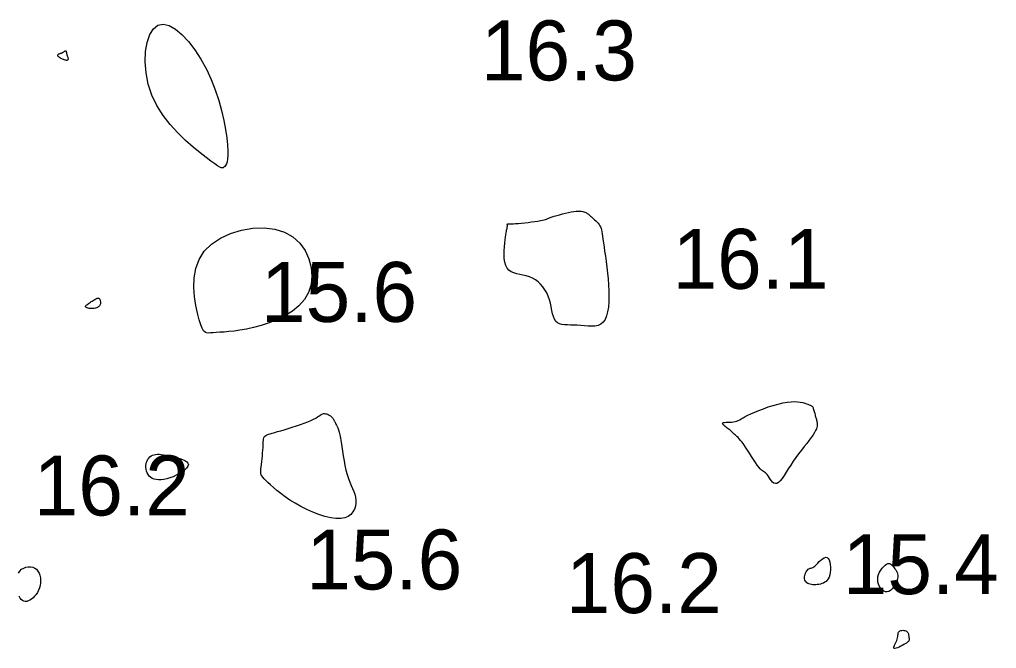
# Model space of a CAD drawing. Extents: x 3040093 to 3056816, y 408076 to 509144.
# Drawn here: x 3045759.4 to 3045840.9, y 434343.9 to 434396.4 of the extents above; entities that cross this region are included whole.
import ezdxf

# ---------------------------------------------------------------- set-up
doc = ezdxf.new("R2010")
doc.units = 0
doc.layers.add('V-CHAN-CONT-EL17', color=7, linetype='Continuous')
doc.layers.add('V-TOPO-SOUN-0610', color=7, linetype='Continuous')

msp = doc.modelspace()

# ---------------------------------------------------------------- linework, layer by layer
at = {"layer": 'V-CHAN-CONT-EL17'}
for points in [[(3045770.173, 434390.988), (3045769.99, 434391.923), (3045769.919, 434392.837), (3045769.953, 434393.698), (3045770.083, 434394.471), (3045770.303, 434395.12), (3045770.605, 434395.611), (3045770.98, 434395.91), (3045771.421, 434395.991), (3045771.912, 434395.869), (3045772.438, 434395.569), (3045772.982, 434395.114), (3045773.528, 434394.53), (3045774.062, 434393.84), (3045774.565, 434393.069), (3045775.024, 434392.241), (3045775.424, 434391.379), (3045775.767, 434390.503), (3045776.054, 434389.63), (3045776.29, 434388.777), (3045776.479, 434387.962), (3045776.622, 434387.203), (3045776.724, 434386.518), (3045776.788, 434385.925), (3045776.817, 434385.435), (3045776.816, 434385.043), (3045776.791, 434384.736), (3045776.748, 434384.502), (3045776.69, 434384.329), (3045776.623, 434384.206), (3045776.554, 434384.121), (3045776.486, 434384.061), (3045776.422, 434384.018), (3045776.352, 434383.998), (3045776.26, 434384.01), (3045776.134, 434384.063), (3045775.959, 434384.166), (3045775.721, 434384.329), (3045775.407, 434384.561), (3045775.001, 434384.87), (3045774.497, 434385.264), (3045773.918, 434385.74), (3045773.292, 434386.294), (3045772.648, 434386.922), (3045772.016, 434387.617), (3045771.423, 434388.377), (3045770.9, 434389.196), (3045770.476, 434390.07)], [(3045763.036, 434393.063), (3045762.964, 434393.098), (3045762.894, 434393.137), (3045762.827, 434393.177), (3045762.767, 434393.219), (3045762.715, 434393.261), (3045762.674, 434393.302), (3045762.646, 434393.341), (3045762.633, 434393.377), (3045762.633, 434393.41), (3045762.644, 434393.439), (3045762.664, 434393.466), (3045762.691, 434393.489), (3045762.723, 434393.51), (3045762.758, 434393.527), (3045762.793, 434393.541), (3045762.827, 434393.553), (3045762.86, 434393.562), (3045762.893, 434393.571), (3045762.925, 434393.579), (3045762.956, 434393.588), (3045762.988, 434393.599), (3045763.02, 434393.613), (3045763.053, 434393.63), (3045763.086, 434393.652), (3045763.12, 434393.676), (3045763.154, 434393.701), (3045763.186, 434393.725), (3045763.216, 434393.746), (3045763.244, 434393.763), (3045763.268, 434393.772), (3045763.289, 434393.773), (3045763.305, 434393.764), (3045763.317, 434393.746), (3045763.326, 434393.718), (3045763.335, 434393.683), (3045763.343, 434393.641), (3045763.352, 434393.593), (3045763.363, 434393.539), (3045763.377, 434393.481), (3045763.395, 434393.419), (3045763.416, 434393.356), (3045763.437, 434393.293), (3045763.456, 434393.231), (3045763.472, 434393.172), (3045763.482, 434393.118), (3045763.485, 434393.071), (3045763.479, 434393.032), (3045763.461, 434393.003), (3045763.433, 434392.983), (3045763.396, 434392.972), (3045763.351, 434392.97), (3045763.298, 434392.975), (3045763.239, 434392.988), (3045763.175, 434393.007), (3045763.107, 434393.032)], [(3045805.664, 434370.898), (3045805.391, 434370.901), (3045805.134, 434370.904), (3045804.896, 434370.915), (3045804.679, 434370.943), (3045804.485, 434370.996), (3045804.317, 434371.081), (3045804.177, 434371.209), (3045804.065, 434371.383), (3045803.977, 434371.599), (3045803.904, 434371.848), (3045803.841, 434372.123), (3045803.78, 434372.414), (3045803.713, 434372.714), (3045803.634, 434373.014), (3045803.535, 434373.306), (3045803.412, 434373.583), (3045803.264, 434373.842), (3045803.093, 434374.081), (3045802.901, 434374.299), (3045802.691, 434374.493), (3045802.463, 434374.662), (3045802.221, 434374.803), (3045801.965, 434374.916), (3045801.7, 434374.999), (3045801.429, 434375.063), (3045801.162, 434375.118), (3045800.903, 434375.174), (3045800.661, 434375.244), (3045800.442, 434375.338), (3045800.253, 434375.467), (3045800.1, 434375.642), (3045799.989, 434375.87), (3045799.915, 434376.142), (3045799.873, 434376.447), (3045799.858, 434376.77), (3045799.863, 434377.1), (3045799.882, 434377.424), (3045799.911, 434377.728), (3045799.943, 434378.002), (3045799.973, 434378.234), (3045800, 434378.426), (3045800.025, 434378.584), (3045800.047, 434378.711), (3045800.067, 434378.812), (3045800.084, 434378.892), (3045800.098, 434378.955), (3045800.109, 434379.006), (3045800.117, 434379.048), (3045800.123, 434379.084), (3045800.127, 434379.115), (3045800.129, 434379.141), (3045800.129, 434379.163), (3045800.129, 434379.184), (3045800.128, 434379.203), (3045800.126, 434379.222), (3045800.125, 434379.241), (3045800.123, 434379.261), (3045800.123, 434379.281), (3045800.125, 434379.299), (3045800.128, 434379.316), (3045800.134, 434379.33), (3045800.143, 434379.34), (3045800.155, 434379.347), (3045800.172, 434379.349), (3045800.198, 434379.348), (3045800.238, 434379.346), (3045800.297, 434379.343), (3045800.38, 434379.341), (3045800.491, 434379.342), (3045800.636, 434379.347), (3045800.819, 434379.358), (3045801.044, 434379.376), (3045801.301, 434379.4), (3045801.578, 434379.429), (3045801.866, 434379.461), (3045802.152, 434379.496), (3045802.426, 434379.533), (3045802.675, 434379.569), (3045802.89, 434379.605), (3045803.062, 434379.638), (3045803.197, 434379.671), (3045803.308, 434379.704), (3045803.404, 434379.739), (3045803.496, 434379.776), (3045803.594, 434379.817), (3045803.71, 434379.863), (3045803.853, 434379.915), (3045804.032, 434379.974), (3045804.24, 434380.037), (3045804.471, 434380.103), (3045804.716, 434380.167), (3045804.966, 434380.229), (3045805.214, 434380.284), (3045805.452, 434380.331), (3045805.672, 434380.366), (3045805.866, 434380.387), (3045806.036, 434380.396), (3045806.184, 434380.394), (3045806.312, 434380.383), (3045806.423, 434380.365), (3045806.518, 434380.34), (3045806.599, 434380.311), (3045806.67, 434380.279), (3045806.731, 434380.246), (3045806.787, 434380.211), (3045806.839, 434380.174), (3045806.889, 434380.132), (3045806.942, 434380.087), (3045806.998, 434380.036), (3045807.061, 434379.979), (3045807.133, 434379.915), (3045807.217, 434379.843), (3045807.308, 434379.765), (3045807.405, 434379.68), (3045807.504, 434379.589), (3045807.601, 434379.494), (3045807.692, 434379.395), (3045807.776, 434379.292), (3045807.847, 434379.186), (3045807.904, 434379.078), (3045807.949, 434378.961), (3045807.985, 434378.831), (3045808.015, 434378.681), (3045808.042, 434378.505), (3045808.07, 434378.298), (3045808.101, 434378.052), (3045808.14, 434377.764), (3045808.187, 434377.427), (3045808.241, 434377.048), (3045808.3, 434376.633), (3045808.36, 434376.188), (3045808.419, 434375.721), (3045808.474, 434375.237), (3045808.522, 434374.744), (3045808.559, 434374.249), (3045808.585, 434373.758), (3045808.594, 434373.279), (3045808.583, 434372.822), (3045808.55, 434372.393), (3045808.49, 434372.001), (3045808.4, 434371.655), (3045808.277, 434371.363), (3045808.117, 434371.133), (3045807.919, 434370.97), (3045807.687, 434370.867), (3045807.428, 434370.812), (3045807.148, 434370.795), (3045806.854, 434370.805), (3045806.552, 434370.831), (3045806.249, 434370.861), (3045805.951, 434370.886)], [(3045775.446, 434377.648), (3045776.188, 434378.147), (3045777.036, 434378.54), (3045777.953, 434378.819), (3045778.899, 434378.976), (3045779.839, 434379.003), (3045780.733, 434378.894), (3045781.544, 434378.641), (3045782.24, 434378.242), (3045782.813, 434377.721), (3045783.26, 434377.105), (3045783.581, 434376.423), (3045783.772, 434375.704), (3045783.831, 434374.977), (3045783.757, 434374.27), (3045783.547, 434373.612), (3045783.204, 434373.025), (3045782.747, 434372.512), (3045782.2, 434372.067), (3045781.587, 434371.685), (3045780.931, 434371.362), (3045780.257, 434371.094), (3045779.588, 434370.875), (3045778.948, 434370.701), (3045778.356, 434370.568), (3045777.817, 434370.469), (3045777.327, 434370.398), (3045776.887, 434370.35), (3045776.494, 434370.318), (3045776.148, 434370.297), (3045775.847, 434370.279), (3045775.591, 434370.261), (3045775.376, 434370.238), (3045775.196, 434370.225), (3045775.044, 434370.24), (3045774.911, 434370.3), (3045774.79, 434370.423), (3045774.674, 434370.626), (3045774.554, 434370.928), (3045774.423, 434371.344), (3045774.279, 434371.887), (3045774.141, 434372.534), (3045774.034, 434373.258), (3045773.984, 434374.031), (3045774.015, 434374.825), (3045774.153, 434375.611), (3045774.422, 434376.362), (3045774.849, 434377.049)], [(3045765.348, 434372.796), (3045765.427, 434372.849), (3045765.506, 434372.901), (3045765.583, 434372.95), (3045765.657, 434372.997), (3045765.727, 434373.04), (3045765.791, 434373.077), (3045765.85, 434373.108), (3045765.9, 434373.131), (3045765.944, 434373.147), (3045765.982, 434373.154), (3045766.015, 434373.154), (3045766.043, 434373.146), (3045766.069, 434373.13), (3045766.093, 434373.105), (3045766.115, 434373.072), (3045766.137, 434373.031), (3045766.158, 434372.982), (3045766.175, 434372.928), (3045766.189, 434372.869), (3045766.196, 434372.807), (3045766.197, 434372.744), (3045766.19, 434372.68), (3045766.173, 434372.618), (3045766.145, 434372.559), (3045766.107, 434372.503), (3045766.059, 434372.451), (3045766, 434372.405), (3045765.932, 434372.364), (3045765.855, 434372.329), (3045765.768, 434372.302), (3045765.673, 434372.283), (3045765.57, 434372.272), (3045765.463, 434372.269), (3045765.356, 434372.274), (3045765.253, 434372.286), (3045765.159, 434372.303), (3045765.077, 434372.326), (3045765.012, 434372.354), (3045764.967, 434372.386), (3045764.947, 434372.421), (3045764.95, 434372.46), (3045764.971, 434372.501), (3045765.01, 434372.546), (3045765.061, 434372.592), (3045765.124, 434372.641), (3045765.195, 434372.691), (3045765.27, 434372.743)], [(3045821.718, 434358.525), (3045821.647, 434358.586), (3045821.575, 434358.636), (3045821.5, 434358.682), (3045821.418, 434358.736), (3045821.327, 434358.807), (3045821.223, 434358.905), (3045821.104, 434359.04), (3045820.967, 434359.219), (3045820.816, 434359.435), (3045820.655, 434359.678), (3045820.488, 434359.937), (3045820.318, 434360.202), (3045820.151, 434360.463), (3045819.99, 434360.71), (3045819.839, 434360.933), (3045819.701, 434361.123), (3045819.577, 434361.282), (3045819.465, 434361.414), (3045819.364, 434361.524), (3045819.274, 434361.615), (3045819.192, 434361.69), (3045819.119, 434361.755), (3045819.053, 434361.812), (3045818.992, 434361.866), (3045818.936, 434361.918), (3045818.88, 434361.969), (3045818.825, 434362.02), (3045818.767, 434362.072), (3045818.704, 434362.126), (3045818.634, 434362.184), (3045818.555, 434362.246), (3045818.466, 434362.313), (3045818.373, 434362.382), (3045818.282, 434362.453), (3045818.199, 434362.522), (3045818.133, 434362.587), (3045818.088, 434362.646), (3045818.072, 434362.696), (3045818.092, 434362.735), (3045818.152, 434362.761), (3045818.246, 434362.777), (3045818.368, 434362.787), (3045818.51, 434362.793), (3045818.664, 434362.798), (3045818.824, 434362.807), (3045818.98, 434362.822), (3045819.127, 434362.847), (3045819.26, 434362.884), (3045819.384, 434362.933), (3045819.508, 434362.996), (3045819.641, 434363.071), (3045819.793, 434363.159), (3045819.971, 434363.26), (3045820.186, 434363.373), (3045820.445, 434363.499), (3045820.754, 434363.636), (3045821.105, 434363.78), (3045821.487, 434363.925), (3045821.888, 434364.066), (3045822.297, 434364.197), (3045822.702, 434364.312), (3045823.092, 434364.406), (3045823.456, 434364.474), (3045823.784, 434364.51), (3045824.076, 434364.52), (3045824.335, 434364.507), (3045824.562, 434364.477), (3045824.759, 434364.436), (3045824.929, 434364.387), (3045825.074, 434364.338), (3045825.195, 434364.292), (3045825.295, 434364.253), (3045825.376, 434364.221), (3045825.442, 434364.192), (3045825.494, 434364.164), (3045825.535, 434364.134), (3045825.569, 434364.1), (3045825.596, 434364.058), (3045825.621, 434364.006), (3045825.646, 434363.943), (3045825.67, 434363.869), (3045825.693, 434363.787), (3045825.717, 434363.7), (3045825.741, 434363.609), (3045825.764, 434363.517), (3045825.787, 434363.426), (3045825.811, 434363.339), (3045825.834, 434363.258), (3045825.856, 434363.181), (3045825.878, 434363.107), (3045825.899, 434363.035), (3045825.918, 434362.964), (3045825.935, 434362.893), (3045825.95, 434362.82), (3045825.962, 434362.744), (3045825.97, 434362.663), (3045825.972, 434362.575), (3045825.963, 434362.477), (3045825.939, 434362.366), (3045825.898, 434362.24), (3045825.834, 434362.096), (3045825.744, 434361.932), (3045825.624, 434361.743), (3045825.473, 434361.529), (3045825.294, 434361.292), (3045825.094, 434361.034), (3045824.877, 434360.759), (3045824.65, 434360.47), (3045824.419, 434360.169), (3045824.19, 434359.859), (3045823.968, 434359.544), (3045823.758, 434359.227), (3045823.561, 434358.917), (3045823.376, 434358.623), (3045823.203, 434358.352), (3045823.039, 434358.116), (3045822.886, 434357.922), (3045822.743, 434357.779), (3045822.608, 434357.697), (3045822.481, 434357.68), (3045822.362, 434357.721), (3045822.25, 434357.805), (3045822.145, 434357.921), (3045822.048, 434358.055), (3045821.956, 434358.195), (3045821.871, 434358.327), (3045821.792, 434358.44)], [(3045781.987, 434356.304), (3045781.588, 434356.574), (3045781.226, 434356.84), (3045780.901, 434357.097), (3045780.614, 434357.341), (3045780.364, 434357.566), (3045780.151, 434357.769), (3045779.975, 434357.944), (3045779.835, 434358.088), (3045779.728, 434358.209), (3045779.651, 434358.313), (3045779.599, 434358.41), (3045779.569, 434358.508), (3045779.557, 434358.615), (3045779.558, 434358.74), (3045779.57, 434358.891), (3045779.588, 434359.073), (3045779.611, 434359.282), (3045779.637, 434359.511), (3045779.664, 434359.751), (3045779.69, 434359.996), (3045779.715, 434360.236), (3045779.735, 434360.466), (3045779.75, 434360.678), (3045779.759, 434360.865), (3045779.764, 434361.028), (3045779.768, 434361.17), (3045779.776, 434361.292), (3045779.79, 434361.397), (3045779.814, 434361.487), (3045779.852, 434361.564), (3045779.906, 434361.63), (3045779.981, 434361.688), (3045780.077, 434361.74), (3045780.198, 434361.79), (3045780.344, 434361.839), (3045780.518, 434361.89), (3045780.72, 434361.947), (3045780.954, 434362.011), (3045781.221, 434362.087), (3045781.52, 434362.174), (3045781.844, 434362.273), (3045782.183, 434362.38), (3045782.526, 434362.492), (3045782.864, 434362.608), (3045783.186, 434362.724), (3045783.483, 434362.838), (3045783.744, 434362.948), (3045783.963, 434363.051), (3045784.142, 434363.146), (3045784.289, 434363.232), (3045784.408, 434363.308), (3045784.506, 434363.373), (3045784.59, 434363.427), (3045784.665, 434363.469), (3045784.737, 434363.497), (3045784.812, 434363.511), (3045784.888, 434363.513), (3045784.966, 434363.504), (3045785.043, 434363.485), (3045785.119, 434363.459), (3045785.191, 434363.428), (3045785.259, 434363.392), (3045785.321, 434363.354), (3045785.377, 434363.316), (3045785.426, 434363.277), (3045785.468, 434363.238), (3045785.506, 434363.199), (3045785.539, 434363.161), (3045785.567, 434363.124), (3045785.592, 434363.088), (3045785.614, 434363.053), (3045785.633, 434363.02), (3045785.651, 434362.987), (3045785.669, 434362.953), (3045785.687, 434362.917), (3045785.708, 434362.876), (3045785.731, 434362.831), (3045785.759, 434362.778), (3045785.792, 434362.717), (3045785.831, 434362.645), (3045785.876, 434362.559), (3045785.925, 434362.453), (3045785.978, 434362.323), (3045786.033, 434362.164), (3045786.09, 434361.971), (3045786.147, 434361.738), (3045786.204, 434361.462), (3045786.259, 434361.141), (3045786.315, 434360.781), (3045786.374, 434360.394), (3045786.436, 434359.99), (3045786.504, 434359.581), (3045786.58, 434359.177), (3045786.666, 434358.788), (3045786.763, 434358.425), (3045786.873, 434358.097), (3045786.99, 434357.8), (3045787.108, 434357.526), (3045787.221, 434357.272), (3045787.323, 434357.029), (3045787.407, 434356.791), (3045787.469, 434356.553), (3045787.501, 434356.308), (3045787.498, 434356.053), (3045787.456, 434355.795), (3045787.372, 434355.544), (3045787.244, 434355.31), (3045787.069, 434355.104), (3045786.842, 434354.936), (3045786.562, 434354.816), (3045786.226, 434354.754), (3045785.832, 434354.757), (3045785.391, 434354.821), (3045784.914, 434354.937), (3045784.414, 434355.098), (3045783.903, 434355.297), (3045783.392, 434355.524), (3045782.895, 434355.773), (3045782.423, 434356.036)], [(3045770.251, 434358.308), (3045770.156, 434358.432), (3045770.081, 434358.57), (3045770.026, 434358.716), (3045769.991, 434358.869), (3045769.974, 434359.024), (3045769.974, 434359.176), (3045769.993, 434359.324), (3045770.028, 434359.462), (3045770.079, 434359.59), (3045770.145, 434359.707), (3045770.224, 434359.812), (3045770.317, 434359.903), (3045770.421, 434359.98), (3045770.535, 434360.041), (3045770.659, 434360.086), (3045770.792, 434360.115), (3045770.935, 434360.127), (3045771.089, 434360.125), (3045771.255, 434360.11), (3045771.434, 434360.084), (3045771.629, 434360.048), (3045771.839, 434360.005), (3045772.067, 434359.954), (3045772.311, 434359.898), (3045772.561, 434359.836), (3045772.806, 434359.766), (3045773.033, 434359.687), (3045773.23, 434359.598), (3045773.385, 434359.498), (3045773.487, 434359.385), (3045773.522, 434359.259), (3045773.483, 434359.119), (3045773.377, 434358.968), (3045773.216, 434358.813), (3045773.01, 434358.659), (3045772.772, 434358.509), (3045772.512, 434358.371), (3045772.243, 434358.248), (3045771.975, 434358.146), (3045771.718, 434358.069), (3045771.474, 434358.017), (3045771.246, 434357.99), (3045771.034, 434357.986), (3045770.839, 434358.007), (3045770.662, 434358.05), (3045770.504, 434358.115), (3045770.367, 434358.201)], [(3045825.185, 434349.361), (3045825.107, 434349.417), (3045825.041, 434349.483), (3045824.987, 434349.556), (3045824.947, 434349.637), (3045824.92, 434349.724), (3045824.908, 434349.817), (3045824.912, 434349.914), (3045824.93, 434350.014), (3045824.962, 434350.115), (3045825.005, 434350.213), (3045825.056, 434350.307), (3045825.111, 434350.393), (3045825.169, 434350.468), (3045825.227, 434350.53), (3045825.282, 434350.575), (3045825.332, 434350.603), (3045825.379, 434350.617), (3045825.427, 434350.626), (3045825.478, 434350.635), (3045825.535, 434350.651), (3045825.601, 434350.68), (3045825.68, 434350.73), (3045825.774, 434350.805), (3045825.885, 434350.911), (3045826.01, 434351.037), (3045826.143, 434351.17), (3045826.282, 434351.3), (3045826.42, 434351.412), (3045826.553, 434351.494), (3045826.677, 434351.535), (3045826.788, 434351.521), (3045826.88, 434351.444), (3045826.954, 434351.312), (3045827.01, 434351.138), (3045827.047, 434350.934), (3045827.066, 434350.712), (3045827.066, 434350.484), (3045827.048, 434350.263), (3045827.012, 434350.061), (3045826.958, 434349.888), (3045826.887, 434349.743), (3045826.802, 434349.624), (3045826.705, 434349.527), (3045826.598, 434349.449), (3045826.482, 434349.388), (3045826.36, 434349.34), (3045826.233, 434349.303), (3045826.105, 434349.273), (3045825.975, 434349.252), (3045825.847, 434349.239), (3045825.721, 434349.235), (3045825.599, 434349.24), (3045825.483, 434349.255), (3045825.374, 434349.28), (3045825.275, 434349.315)], [(3045831.658, 434348.656), (3045831.515, 434348.715), (3045831.38, 434348.814), (3045831.259, 434348.948), (3045831.157, 434349.109), (3045831.079, 434349.291), (3045831.03, 434349.488), (3045831.015, 434349.692), (3045831.038, 434349.897), (3045831.093, 434350.099), (3045831.175, 434350.292), (3045831.277, 434350.471), (3045831.393, 434350.633), (3045831.515, 434350.772), (3045831.638, 434350.884), (3045831.754, 434350.964), (3045831.859, 434351.008), (3045831.954, 434351.019), (3045832.039, 434351.003), (3045832.117, 434350.964), (3045832.189, 434350.905), (3045832.257, 434350.832), (3045832.323, 434350.749), (3045832.388, 434350.661), (3045832.454, 434350.57), (3045832.518, 434350.477), (3045832.577, 434350.378), (3045832.626, 434350.272), (3045832.663, 434350.157), (3045832.683, 434350.031), (3045832.684, 434349.892), (3045832.663, 434349.737), (3045832.615, 434349.567), (3045832.545, 434349.389), (3045832.454, 434349.211), (3045832.346, 434349.043), (3045832.224, 434348.894), (3045832.091, 434348.771), (3045831.951, 434348.685), (3045831.805, 434348.645)], [(3045832.349, 434343.957), (3045832.346, 434344.006), (3045832.368, 434344.075), (3045832.406, 434344.161), (3045832.456, 434344.259), (3045832.51, 434344.367), (3045832.564, 434344.48), (3045832.609, 434344.596), (3045832.642, 434344.711), (3045832.665, 434344.823), (3045832.682, 434344.931), (3045832.696, 434345.033), (3045832.712, 434345.126), (3045832.732, 434345.21), (3045832.763, 434345.283), (3045832.806, 434345.343), (3045832.864, 434345.388), (3045832.936, 434345.419), (3045833.017, 434345.437), (3045833.102, 434345.443), (3045833.19, 434345.438), (3045833.274, 434345.422), (3045833.353, 434345.397), (3045833.42, 434345.362), (3045833.475, 434345.32), (3045833.517, 434345.272), (3045833.548, 434345.218), (3045833.571, 434345.162), (3045833.587, 434345.105), (3045833.597, 434345.048), (3045833.604, 434344.993), (3045833.609, 434344.942), (3045833.614, 434344.896), (3045833.62, 434344.854), (3045833.624, 434344.817), (3045833.628, 434344.782), (3045833.631, 434344.75), (3045833.633, 434344.719), (3045833.633, 434344.689), (3045833.631, 434344.659), (3045833.626, 434344.629), (3045833.616, 434344.597), (3045833.599, 434344.562), (3045833.572, 434344.524), (3045833.533, 434344.481), (3045833.478, 434344.434), (3045833.406, 434344.381), (3045833.313, 434344.32), (3045833.199, 434344.253), (3045833.069, 434344.183), (3045832.932, 434344.113), (3045832.793, 434344.049), (3045832.662, 434343.994), (3045832.545, 434343.954), (3045832.449, 434343.931), (3045832.382, 434343.931)]]:
    msp.add_lwpolyline(points, close=True, dxfattribs=at)
msp.add_lwpolyline([(3045759.341, 434350.206), (3045759.463, 434350.386), (3045759.615, 434350.53), (3045759.788, 434350.64), (3045759.975, 434350.713), (3045760.168, 434350.75), (3045760.36, 434350.75), (3045760.543, 434350.714), (3045760.709, 434350.64), (3045760.852, 434350.53), (3045760.97, 434350.388), (3045761.064, 434350.22), (3045761.133, 434350.032), (3045761.176, 434349.829), (3045761.195, 434349.617), (3045761.189, 434349.402), (3045761.157, 434349.19), (3045761.101, 434348.985), (3045761.022, 434348.79), (3045760.926, 434348.608), (3045760.815, 434348.44), (3045760.693, 434348.289), (3045760.563, 434348.157), (3045760.429, 434348.045), (3045760.295, 434347.956), (3045760.163, 434347.893), (3045760.035, 434347.856), (3045759.912, 434347.848), (3045759.795, 434347.87), (3045759.684, 434347.924), (3045759.58, 434348.012), (3045759.484, 434348.136), (3045759.397, 434348.297)], dxfattribs=at)

# ---------------------------------------------------------------- texts
at = {"layer": 'V-TOPO-SOUN-0610'}
for s, p in [('16.3 ', (3045797.923, 434391.3)), ('16.1 ', (3045813.903, 434373.92)), ('15.6 ', (3045779.583, 434371.16)), ('16.2 ', (3045760.623, 434355.02)), ('15.6 ', (3045783.353, 434348.85)), ('15.4 ', (3045828.103, 434348.46)), ('16.2 ', (3045805.003, 434346.88))]:
    msp.add_text(s, height=5, dxfattribs=at).set_placement(p)

doc.saveas('drawing.dxf')
